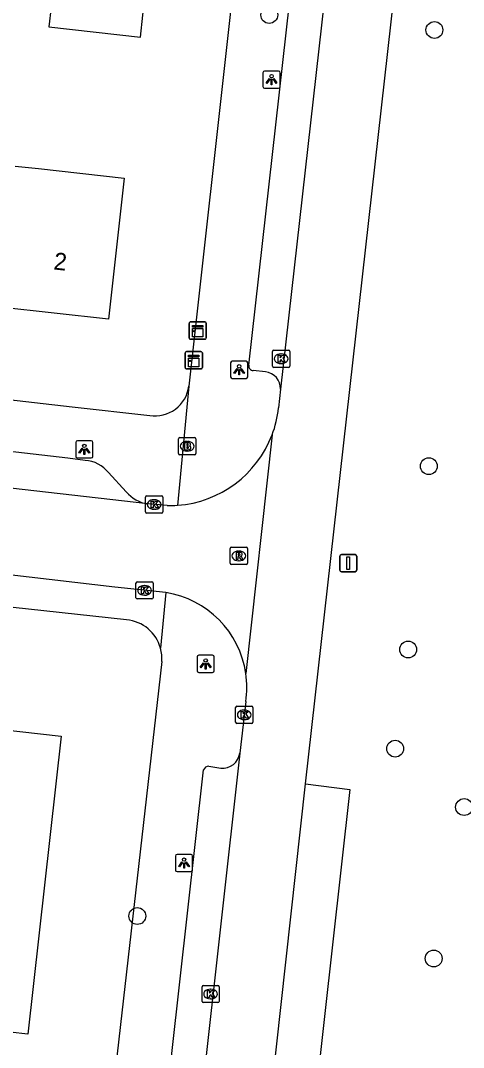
# Model space of a CAD drawing. Extents: x 161928 to 163055, y 386475 to 387428.
# Drawn here: x 162285.4 to 162311.1, y 387004.7 to 387064.4 of the extents above; entities that cross this region are included whole.
import ezdxf

# ---------------------------------------------------------------- set-up
doc = ezdxf.new("R2010")
doc.units = 0
for name, color, linetype in [('IMGEO_Boom', 7, 'Continuous'), ('IMGEO_Brandkraan', 7, 'Continuous'), ('IMGEO_Kast', 7, 'Continuous'), ('IMGEO_Kolk', 7, 'Continuous'), ('IMGEO_Lichtpunt', 7, 'Continuous'), ('IMGEO_Pand', 7, 'Continuous'), ('IMGEO_Pand_nummerreeks', 7, 'Continuous'), ('IMGEO_Parkeervlak_open', 7, 'Continuous'), ('IMGEO_Rijbaan_lokaal_open', 7, 'Continuous'), ('IMGEO_Rioolput', 7, 'Continuous'), ('IMGEO_Verkeersbordpaal', 7, 'Continuous'), ('IMGEO_Voetpad_open', 7, 'Continuous')]:
    doc.layers.add(name, color=color, linetype=linetype)

msp = doc.modelspace()

# ---------------------------------------------------------------- linework, layer by layer
at = {"layer": 'IMGEO_Boom'}
for centre in [(162299.864, 387064.689), (162309.455, 387063.817), (162309.128, 387038.487), (162307.931, 387027.834), (162307.177, 387022.077), (162311.177, 387018.684), (162292.201, 387012.356), (162309.414, 387009.889)]:
    msp.add_circle(centre, 0.489, dxfattribs=at)
at = {"layer": 'IMGEO_Brandkraan'}
for p, q in [((162294.599, 387039.214), (162294.599, 387040.066)), ((162294.674, 387040.14), (162295.526, 387040.14)), ((162295.6, 387040.066), (162295.6, 387039.214)), ((162295.087, 387039.92), (162295.112, 387039.92)), ((162295.526, 387039.14), (162294.674, 387039.14)), ((162295.11, 387039.36), (162295.085, 387039.36))]:
    msp.add_line(p, q, dxfattribs=at)
for points in [[(162294.599, 387039.214), (162294.599, 387040.066)], [(162294.674, 387040.14), (162295.526, 387040.14)], [(162295.6, 387040.066), (162295.6, 387039.214)], [(162294.947, 387039.84), (162294.947, 387039.44), (162295.16, 387039.44)], [(162295.178, 387039.84), (162294.947, 387039.84)], [(162295.126, 387039.759), (162295.072, 387039.759), (162295.072, 387039.683)], [(162295.072, 387039.683), (162295.125, 387039.683)], [(162295.134, 387039.607), (162295.072, 387039.607), (162295.072, 387039.526)], [(162295.072, 387039.526), (162295.134, 387039.526)], [(162295.526, 387039.14), (162294.674, 387039.14)]]:
    msp.add_lwpolyline(points, dxfattribs=at)
for centre, radius, start, end in [((162294.676, 387040.064), 0.0765, 91.55205, 178.44795), ((162294.676, 387040.064), 0.0765, 91.55205, 178.44795), ((162295.524, 387040.064), 0.0765, 1.55205, 88.44795), ((162295.524, 387040.064), 0.0765, 1.55205, 88.44795), ((162295.127, 387039.721), 0.0379, 267.82845, 90.93552), ((162295.135, 387039.566), 0.0404, 269.87594, 90.50774), ((162295.166, 387039.691), 0.251, 268.66757, 293.53466), ((162295.182, 387039.695), 0.145, 59.4692, 91.53667), ((162295.207, 387039.742), 0.0922, 285.51372, 58.15012), ((162295.212, 387039.55), 0.105, 301.31148, 78.98903), ((162294.676, 387039.216), 0.0765, 181.55205, 268.44795), ((162294.676, 387039.216), 0.0765, 181.55205, 268.44795), ((162295.524, 387039.216), 0.0765, 271.55205, 358.44795), ((162295.524, 387039.216), 0.0765, 271.55205, 358.44795)]:
    msp.add_arc(centre, radius, start, end, dxfattribs=at)
for centre, major_axis, ratio, start_param, end_param in [((162295.086, 387039.64), (-0.387, 0.002), 0.722429, 4.712389, 7.853982), ((162295.111, 387039.64), (-0.39, 0.002), 0.717154, 1.570796, 4.712389)]:
    msp.add_ellipse(centre, major_axis=major_axis, ratio=ratio, start_param=start_param, end_param=end_param, dxfattribs=at)
at = {"layer": 'IMGEO_Kast'}
for p, q in [((162295.206, 387045.935), (162295.206, 387046.776)), ((162295.206, 387046.776), (162295.206, 387045.935)), ((162295.281, 387046.86), (162296.122, 387046.86)), ((162296.122, 387046.86), (162295.281, 387046.86)), ((162296.206, 387046.785), (162296.206, 387045.944)), ((162296.206, 387045.944), (162296.206, 387046.785)), ((162296.131, 387045.86), (162295.29, 387045.86)), ((162295.29, 387045.86), (162296.131, 387045.86)), ((162294.982, 387044.209), (162294.982, 387045.05)), ((162294.982, 387045.05), (162294.982, 387044.209)), ((162295.057, 387045.134), (162295.898, 387045.134)), ((162295.898, 387045.134), (162295.057, 387045.134)), ((162295.982, 387045.059), (162295.982, 387044.218)), ((162295.982, 387044.218), (162295.982, 387045.059)), ((162295.907, 387044.134), (162295.066, 387044.134)), ((162295.066, 387044.134), (162295.907, 387044.134))]:
    msp.add_line(p, q, dxfattribs=at)
for points in [[(162295.401, 387046.65), (162296.001, 387046.65), (162296.001, 387046.565), (162295.401, 387046.565), (162295.401, 387046.65)], [(162295.401, 387046.475), (162296.001, 387046.475), (162296.001, 387045.986), (162295.401, 387045.986), (162295.401, 387046.475)], [(162295.177, 387044.924), (162295.777, 387044.924), (162295.777, 387044.839), (162295.177, 387044.839), (162295.177, 387044.924)], [(162295.177, 387044.749), (162295.777, 387044.749), (162295.777, 387044.26), (162295.177, 387044.26), (162295.177, 387044.749)]]:
    msp.add_lwpolyline(points, dxfattribs=at)
for centre in [(162295.485, 387046.324), (162295.261, 387044.598)]:
    msp.add_circle(centre, 0.0377, dxfattribs=at)
for centre, start, end in [((162295.284, 387046.782), 92.4484, 184.28452), ((162295.284, 387046.782), 92.4484, 184.28452), ((162296.128, 387046.782), 2.4484, 94.28452), ((162296.128, 387046.782), 2.4484, 94.28452), ((162295.284, 387045.938), 182.4484, 274.28452), ((162295.284, 387045.938), 182.4484, 274.28452), ((162296.128, 387045.938), 272.4484, 4.28452), ((162296.128, 387045.938), 272.4484, 4.28452), ((162295.06, 387045.056), 92.4484, 184.28452), ((162295.06, 387045.056), 92.4484, 184.28452), ((162295.904, 387045.056), 2.4484, 94.28452), ((162295.904, 387045.056), 2.4484, 94.28452), ((162295.06, 387044.212), 182.4484, 274.28452), ((162295.06, 387044.212), 182.4484, 274.28452), ((162295.904, 387044.212), 272.4484, 4.28452), ((162295.904, 387044.212), 272.4484, 4.28452)]:
    msp.add_arc(centre, 0.0779, start, end, dxfattribs=at)
at = {"layer": 'IMGEO_Kolk'}
for p, q in [((162300.052, 387044.298), (162300.052, 387045.15)), ((162300.127, 387045.224), (162300.979, 387045.224)), ((162300.54, 387045.004), (162300.565, 387045.004)), ((162301.053, 387045.15), (162301.053, 387044.298)), ((162300.979, 387044.224), (162300.127, 387044.224)), ((162300.563, 387044.444), (162300.538, 387044.444)), ((162292.683, 387035.832), (162292.683, 387036.684)), ((162292.758, 387036.758), (162293.61, 387036.758)), ((162293.171, 387036.538), (162293.196, 387036.538)), ((162293.684, 387036.684), (162293.684, 387035.832)), ((162293.194, 387035.978), (162293.169, 387035.978)), ((162293.61, 387035.758), (162292.758, 387035.758)), ((162292.124, 387030.845), (162292.124, 387031.697)), ((162292.199, 387031.771), (162293.051, 387031.771)), ((162293.125, 387031.697), (162293.125, 387030.845)), ((162292.612, 387031.551), (162292.637, 387031.551)), ((162293.051, 387030.771), (162292.199, 387030.771)), ((162292.635, 387030.991), (162292.61, 387030.991)), ((162297.988, 387024.541), (162298.84, 387024.541)), ((162297.913, 387023.615), (162297.913, 387024.467)), ((162298.401, 387024.321), (162298.426, 387024.321)), ((162298.914, 387024.467), (162298.914, 387023.615)), ((162298.84, 387023.541), (162297.988, 387023.541)), ((162298.424, 387023.761), (162298.399, 387023.761)), ((162295.959, 387007.4), (162295.959, 387008.252)), ((162296.034, 387008.326), (162296.886, 387008.326)), ((162296.447, 387008.106), (162296.472, 387008.106)), ((162296.96, 387008.252), (162296.96, 387007.4)), ((162296.886, 387007.326), (162296.034, 387007.326)), ((162296.47, 387007.546), (162296.445, 387007.546))]:
    msp.add_line(p, q, dxfattribs=at)
for points in [[(162300.052, 387044.298), (162300.052, 387045.15)], [(162300.127, 387045.224), (162300.979, 387045.224)], [(162300.373, 387044.924), (162300.496, 387044.924), (162300.496, 387044.773), (162300.626, 387044.924), (162300.79, 387044.924), (162300.644, 387044.773), (162300.797, 387044.524), (162300.645, 387044.524), (162300.56, 387044.688), (162300.496, 387044.621), (162300.496, 387044.524), (162300.373, 387044.524), (162300.373, 387044.924)], [(162301.053, 387045.15), (162301.053, 387044.298)], [(162300.979, 387044.224), (162300.127, 387044.224)], [(162292.683, 387035.832), (162292.683, 387036.684)], [(162292.758, 387036.758), (162293.61, 387036.758)], [(162293.004, 387036.458), (162293.127, 387036.458), (162293.127, 387036.307), (162293.257, 387036.458), (162293.421, 387036.458), (162293.275, 387036.307), (162293.428, 387036.058), (162293.276, 387036.058), (162293.191, 387036.222), (162293.127, 387036.155), (162293.127, 387036.058), (162293.004, 387036.058), (162293.004, 387036.458)], [(162293.684, 387036.684), (162293.684, 387035.832)], [(162293.61, 387035.758), (162292.758, 387035.758)], [(162292.124, 387030.845), (162292.124, 387031.697)], [(162292.199, 387031.771), (162293.051, 387031.771)], [(162293.125, 387031.697), (162293.125, 387030.845)], [(162292.445, 387031.471), (162292.568, 387031.471), (162292.568, 387031.32), (162292.698, 387031.471), (162292.862, 387031.471), (162292.716, 387031.32), (162292.869, 387031.071), (162292.717, 387031.071), (162292.632, 387031.235), (162292.568, 387031.168), (162292.568, 387031.071), (162292.445, 387031.071), (162292.445, 387031.471)], [(162293.051, 387030.771), (162292.199, 387030.771)], [(162297.988, 387024.541), (162298.84, 387024.541)], [(162297.913, 387023.615), (162297.913, 387024.467)], [(162298.234, 387024.241), (162298.357, 387024.241), (162298.357, 387024.09), (162298.487, 387024.241), (162298.651, 387024.241), (162298.505, 387024.09), (162298.658, 387023.841), (162298.506, 387023.841), (162298.421, 387024.005), (162298.357, 387023.938), (162298.357, 387023.841), (162298.234, 387023.841), (162298.234, 387024.241)], [(162298.914, 387024.467), (162298.914, 387023.615)], [(162298.84, 387023.541), (162297.988, 387023.541)], [(162295.959, 387007.4), (162295.959, 387008.252)], [(162296.034, 387008.326), (162296.886, 387008.326)], [(162296.28, 387008.026), (162296.403, 387008.026), (162296.403, 387007.875), (162296.533, 387008.026), (162296.697, 387008.026), (162296.551, 387007.875), (162296.704, 387007.626), (162296.552, 387007.626), (162296.467, 387007.79), (162296.403, 387007.723), (162296.403, 387007.626), (162296.28, 387007.626), (162296.28, 387008.026)], [(162296.96, 387008.252), (162296.96, 387007.4)], [(162296.886, 387007.326), (162296.034, 387007.326)]]:
    msp.add_lwpolyline(points, dxfattribs=at)
for centre, start, end in [((162300.129, 387045.148), 91.55205, 178.44795), ((162300.129, 387045.148), 91.55205, 178.44795), ((162300.977, 387045.148), 1.55205, 88.44795), ((162300.977, 387045.148), 1.55205, 88.44795), ((162300.129, 387044.3), 181.55205, 268.44795), ((162300.129, 387044.3), 181.55205, 268.44795), ((162300.977, 387044.3), 271.55205, 358.44795), ((162300.977, 387044.3), 271.55205, 358.44795), ((162292.76, 387036.682), 91.55205, 178.44795), ((162292.76, 387036.682), 91.55205, 178.44795), ((162293.608, 387036.682), 1.55205, 88.44795), ((162293.608, 387036.682), 1.55205, 88.44795), ((162292.76, 387035.834), 181.55205, 268.44795), ((162292.76, 387035.834), 181.55205, 268.44795), ((162293.608, 387035.834), 271.55205, 358.44795), ((162293.608, 387035.834), 271.55205, 358.44795), ((162292.201, 387031.695), 91.55205, 178.44795), ((162292.201, 387031.695), 91.55205, 178.44795), ((162293.049, 387031.695), 1.55205, 88.44795), ((162293.049, 387031.695), 1.55205, 88.44795), ((162292.201, 387030.847), 181.55205, 268.44795), ((162292.201, 387030.847), 181.55205, 268.44795), ((162293.049, 387030.847), 271.55205, 358.44795), ((162293.049, 387030.847), 271.55205, 358.44795), ((162297.99, 387024.465), 91.55205, 178.44795), ((162297.99, 387024.465), 91.55205, 178.44795), ((162298.838, 387024.465), 1.55205, 88.44795), ((162298.838, 387024.465), 1.55205, 88.44795), ((162297.99, 387023.617), 181.55205, 268.44795), ((162297.99, 387023.617), 181.55205, 268.44795), ((162298.838, 387023.617), 271.55205, 358.44795), ((162298.838, 387023.617), 271.55205, 358.44795), ((162296.036, 387008.25), 91.55205, 178.44795), ((162296.036, 387008.25), 91.55205, 178.44795), ((162296.884, 387008.25), 1.55205, 88.44795), ((162296.884, 387008.25), 1.55205, 88.44795), ((162296.036, 387007.402), 181.55205, 268.44795), ((162296.036, 387007.402), 181.55205, 268.44795), ((162296.884, 387007.402), 271.55205, 358.44795), ((162296.884, 387007.402), 271.55205, 358.44795)]:
    msp.add_arc(centre, 0.0765, start, end, dxfattribs=at)
for centre, major_axis, ratio, start_param, end_param in [((162300.539, 387044.724), (-0.387, 0.002), 0.722429, 4.712389, 7.853982), ((162300.564, 387044.724), (-0.39, 0.002), 0.717154, 1.570796, 4.712389), ((162293.17, 387036.258), (-0.387, 0.002), 0.722429, 4.712389, 7.853982), ((162293.195, 387036.258), (-0.39, 0.002), 0.717154, 1.570796, 4.712389), ((162292.611, 387031.271), (-0.387, 0.002), 0.722429, 4.712389, 7.853982), ((162292.636, 387031.271), (-0.39, 0.002), 0.717154, 1.570796, 4.712389), ((162298.4, 387024.041), (-0.387, 0.002), 0.722429, 4.712389, 7.853982), ((162298.425, 387024.041), (-0.39, 0.002), 0.717154, 1.570796, 4.712389), ((162296.446, 387007.826), (-0.387, 0.002), 0.722429, 4.712389, 7.853982), ((162296.471, 387007.826), (-0.39, 0.002), 0.717154, 1.570796, 4.712389)]:
    msp.add_ellipse(centre, major_axis=major_axis, ratio=ratio, start_param=start_param, end_param=end_param, dxfattribs=at)
at = {"layer": 'IMGEO_Lichtpunt'}
for p, q in [((162299.5, 387061.338), (162299.5, 387060.531)), ((162299.5, 387061.338), (162299.5, 387060.531)), ((162300.402, 387061.433), (162299.594, 387061.433)), ((162300.402, 387061.433), (162299.594, 387061.433)), ((162300.496, 387060.531), (162300.496, 387061.338)), ((162300.496, 387060.531), (162300.496, 387061.338)), ((162299.594, 387060.437), (162300.402, 387060.437)), ((162299.594, 387060.437), (162300.402, 387060.437)), ((162297.618, 387044.486), (162297.618, 387043.679)), ((162297.618, 387044.486), (162297.618, 387043.679)), ((162298.52, 387044.581), (162297.712, 387044.581)), ((162298.52, 387044.581), (162297.712, 387044.581)), ((162298.614, 387043.679), (162298.614, 387044.486)), ((162298.614, 387043.679), (162298.614, 387044.486)), ((162297.712, 387043.585), (162298.52, 387043.585)), ((162297.712, 387043.585), (162298.52, 387043.585)), ((162288.626, 387039.861), (162288.626, 387039.054)), ((162288.626, 387039.861), (162288.626, 387039.054)), ((162289.528, 387039.956), (162288.72, 387039.956)), ((162289.528, 387039.956), (162288.72, 387039.956)), ((162289.622, 387039.054), (162289.622, 387039.861)), ((162289.622, 387039.054), (162289.622, 387039.861)), ((162288.72, 387038.96), (162289.528, 387038.96)), ((162288.72, 387038.96), (162289.528, 387038.96)), ((162296.576, 387027.499), (162295.768, 387027.499)), ((162296.576, 387027.499), (162295.768, 387027.499)), ((162295.674, 387027.404), (162295.674, 387026.597)), ((162295.674, 387027.404), (162295.674, 387026.597)), ((162296.67, 387026.597), (162296.67, 387027.404)), ((162296.67, 387026.597), (162296.67, 387027.404)), ((162295.768, 387026.503), (162296.576, 387026.503)), ((162295.768, 387026.503), (162296.576, 387026.503)), ((162294.419, 387015.836), (162294.419, 387015.029)), ((162294.419, 387015.836), (162294.419, 387015.029)), ((162295.321, 387015.931), (162294.513, 387015.931)), ((162295.321, 387015.931), (162294.513, 387015.931)), ((162295.415, 387015.029), (162295.415, 387015.836)), ((162295.415, 387015.029), (162295.415, 387015.836)), ((162294.513, 387014.935), (162295.321, 387014.935)), ((162294.513, 387014.935), (162295.321, 387014.935))]:
    msp.add_line(p, q, dxfattribs=at)
for points in [[(162299.874, 387061.002), (162299.913, 387060.974), (162299.725, 387060.712), (162299.687, 387060.739), (162299.874, 387061.002)], [(162299.976, 387060.954), (162300.023, 387060.954), (162300.023, 387060.632), (162299.976, 387060.632), (162299.976, 387060.954)], [(162300.086, 387060.974), (162300.124, 387061.001), (162300.311, 387060.739), (162300.272, 387060.711), (162300.086, 387060.974)], [(162297.992, 387044.15), (162298.031, 387044.122), (162297.843, 387043.86), (162297.805, 387043.887), (162297.992, 387044.15)], [(162298.094, 387044.102), (162298.141, 387044.102), (162298.141, 387043.78), (162298.094, 387043.78), (162298.094, 387044.102)], [(162298.204, 387044.122), (162298.242, 387044.149), (162298.429, 387043.887), (162298.39, 387043.859), (162298.204, 387044.122)], [(162289, 387039.525), (162289.039, 387039.497), (162288.851, 387039.235), (162288.813, 387039.262), (162289, 387039.525)], [(162289.102, 387039.477), (162289.149, 387039.477), (162289.149, 387039.155), (162289.102, 387039.155), (162289.102, 387039.477)], [(162289.212, 387039.497), (162289.25, 387039.524), (162289.437, 387039.262), (162289.398, 387039.234), (162289.212, 387039.497)], [(162296.048, 387027.068), (162296.087, 387027.04), (162295.899, 387026.778), (162295.861, 387026.805), (162296.048, 387027.068)], [(162296.15, 387027.02), (162296.197, 387027.02), (162296.197, 387026.698), (162296.15, 387026.698), (162296.15, 387027.02)], [(162296.26, 387027.04), (162296.298, 387027.067), (162296.485, 387026.805), (162296.446, 387026.777), (162296.26, 387027.04)], [(162294.793, 387015.5), (162294.832, 387015.472), (162294.644, 387015.21), (162294.606, 387015.237), (162294.793, 387015.5)], [(162294.895, 387015.452), (162294.942, 387015.452), (162294.942, 387015.13), (162294.895, 387015.13), (162294.895, 387015.452)], [(162295.005, 387015.472), (162295.043, 387015.499), (162295.23, 387015.237), (162295.191, 387015.209), (162295.005, 387015.472)]]:
    msp.add_lwpolyline(points, dxfattribs=at)
for centre in [(162299.999, 387061.136), (162298.117, 387044.284), (162289.125, 387039.659), (162296.173, 387027.202), (162294.918, 387015.634)]:
    msp.add_circle(centre, 0.0994, dxfattribs=at)
for centre, start, end in [((162299.594, 387061.338), 90, 180), ((162299.594, 387061.338), 90, 180), ((162300.402, 387061.338), 0, 90), ((162300.402, 387061.338), 0, 90), ((162299.594, 387060.531), 180, 270), ((162299.594, 387060.531), 180, 270), ((162300.402, 387060.531), 270, 0), ((162300.402, 387060.531), 270, 360), ((162297.712, 387044.486), 90, 180), ((162297.712, 387044.486), 90, 180), ((162298.52, 387044.486), 0, 90), ((162298.52, 387044.486), 0, 90), ((162297.712, 387043.679), 180, 270), ((162297.712, 387043.679), 180, 270), ((162298.52, 387043.679), 270, 0), ((162298.52, 387043.679), 270, 360), ((162288.72, 387039.861), 90, 180), ((162288.72, 387039.861), 90, 180), ((162289.528, 387039.861), 0, 90), ((162289.528, 387039.861), 0, 90), ((162288.72, 387039.054), 180, 270), ((162288.72, 387039.054), 180, 270), ((162289.528, 387039.054), 270, 0), ((162289.528, 387039.054), 270, 360), ((162295.768, 387027.404), 90, 180), ((162295.768, 387027.404), 90, 180), ((162296.576, 387027.404), 0, 90), ((162296.576, 387027.404), 0, 90), ((162295.768, 387026.597), 180, 270), ((162295.768, 387026.597), 180, 270), ((162296.576, 387026.597), 270, 0), ((162296.576, 387026.597), 270, 360), ((162294.513, 387015.836), 90, 180), ((162294.513, 387015.836), 90, 180), ((162295.321, 387015.836), 0, 90), ((162295.321, 387015.836), 0, 90), ((162294.513, 387015.029), 180, 270), ((162294.513, 387015.029), 180, 270), ((162295.321, 387015.029), 270, 0), ((162295.321, 387015.029), 270, 360)]:
    msp.add_arc(centre, 0.0946, start, end, dxfattribs=at)
at = {"layer": 'IMGEO_Pand'}
for points in [[(162287.329, 387066.347), (162287.066, 387064.003), (162292.38, 387063.408), (162292.667, 387065.968)], [(162285.114, 387055.914), (162286.469, 387055.764), (162291.438, 387055.212), (162290.528, 387047.022), (162284.204, 387047.724)], [(162271.046, 387016.413), (162271.412, 387019.683), (162270.574, 387019.777), (162270.689, 387020.81), (162271.548, 387020.714), (162271.979, 387024.574), (162287.783, 387022.808), (162285.849, 387005.499), (162277.625, 387006.418), (162277.472, 387005.048), (162268.663, 387006.033)]]:
    msp.add_lwpolyline(points, dxfattribs=at)
at = {"layer": 'IMGEO_Parkeervlak_open'}
msp.add_lwpolyline([(162301.966, 387020.029), (162304.536, 387019.704), (162302.547, 387001.835), (162299.988, 387002.128)], dxfattribs=at)
at = {"layer": 'IMGEO_Rijbaan_lokaal_open'}
for points in [[(162309.861, 387125.998), (162300.517, 387042.959)], [(162301.966, 387020.029), (162309.685, 387088.77)], [(162292.807, 387036.295), (162209.297, 387045.816)], [(162300.517, 387042.959), (162300.407, 387041.864)], [(162300.028, 387040.299), (162298.503, 387026.445)], [(162293.928, 387036.193), (162292.807, 387036.295)], [(162293.855, 387031.139), (162290.902, 387031.456), (162256.711, 387035.451)], [(162298.5, 387024.808), (162298.15, 387021.823)], [(162298.15, 387021.823), (162295.968, 387002.165), (162294.227, 386986.475)], [(162299.988, 387002.128), (162301.966, 387020.029)]]:
    msp.add_lwpolyline(points, dxfattribs=at)
for centre, radius, start, end in [((162294.072, 387042.57), 6.374, 339.13025, 353.64301), ((162294.065, 387042.574), 6.382, 274.23289, 339.11867), ((162294.058, 387042.803), 6.611, 268.8711, 274.14377), ((162292.992, 387025.636), 5.57, 8.35079, 81.08496), ((162292.995, 387025.637), 5.567, 351.44016, 8.34984)]:
    msp.add_arc(centre, radius, start, end, dxfattribs=at)
at = {"layer": 'IMGEO_Rioolput'}
for p, q in [((162297.598, 387032.848), (162297.598, 387033.7)), ((162297.673, 387033.774), (162298.525, 387033.774)), ((162298.086, 387033.554), (162298.111, 387033.554)), ((162298.599, 387033.7), (162298.599, 387032.848)), ((162298.109, 387032.994), (162298.084, 387032.994)), ((162298.525, 387032.774), (162297.673, 387032.774))]:
    msp.add_line(p, q, dxfattribs=at)
for points in [[(162297.598, 387032.848), (162297.598, 387033.7)], [(162297.673, 387033.774), (162298.525, 387033.774)], [(162298.187, 387033.472), (162297.935, 387033.474), (162297.935, 387033.074)], [(162298.599, 387033.7), (162298.599, 387032.848)], [(162297.935, 387033.074), (162298.059, 387033.074), (162298.059, 387033.236), (162298.07, 387033.236)], [(162298.113, 387033.393), (162298.059, 387033.393), (162298.059, 387033.312)], [(162298.059, 387033.312), (162298.111, 387033.312)], [(162298.117, 387033.207), (162298.188, 387033.074), (162298.328, 387033.074), (162298.263, 387033.2)], [(162298.525, 387032.774), (162297.673, 387032.774)]]:
    msp.add_lwpolyline(points, dxfattribs=at)
for centre, radius, start, end in [((162297.675, 387033.698), 0.0765, 91.55205, 178.44795), ((162297.675, 387033.698), 0.0765, 91.55205, 178.44795), ((162298.186, 387033.362), 0.109, 350.36119, 89.41601), ((162298.523, 387033.698), 0.0765, 1.55205, 88.44795), ((162298.523, 387033.698), 0.0765, 1.55205, 88.44795), ((162297.675, 387032.85), 0.0765, 181.55205, 268.44795), ((162297.675, 387032.85), 0.0765, 181.55205, 268.44795), ((162298.069, 387033.183), 0.0533, 26.02933, 88.69889), ((162298.095, 387033.501), 0.19, 274.7715, 282.96867), ((162298.119, 387033.297), 0.0964, 77.00612, 93.18647), ((162298.133, 387033.354), 0.0378, 276.66336, 79.67722), ((162298.184, 387033.362), 0.112, 277.58423, 350.98172), ((162298.168, 387033.147), 0.108, 29.51342, 73.79051), ((162298.523, 387032.85), 0.0765, 271.55205, 358.44795), ((162298.523, 387032.85), 0.0765, 271.55205, 358.44795)]:
    msp.add_arc(centre, radius, start, end, dxfattribs=at)
for centre, major_axis, ratio, start_param, end_param in [((162298.085, 387033.274), (-0.387, 0.002), 0.722429, 4.712389, 7.853982), ((162298.11, 387033.274), (-0.39, 0.002), 0.717154, 1.570796, 4.712389)]:
    msp.add_ellipse(centre, major_axis=major_axis, ratio=ratio, start_param=start_param, end_param=end_param, dxfattribs=at)
at = {"layer": 'IMGEO_Verkeersbordpaal'}
for p, q in [((162303.958, 387032.452), (162303.958, 387033.252)), ((162303.958, 387033.252), (162303.958, 387032.452)), ((162304.058, 387033.352), (162304.848, 387033.352)), ((162304.848, 387033.352), (162304.058, 387033.352)), ((162304.948, 387033.252), (162304.948, 387032.452)), ((162304.948, 387032.452), (162304.948, 387033.252)), ((162304.848, 387032.352), (162304.058, 387032.352)), ((162304.058, 387032.352), (162304.848, 387032.352))]:
    msp.add_line(p, q, dxfattribs=at)
msp.add_lwpolyline([(162304.378, 387033.227), (162304.528, 387033.227), (162304.528, 387032.477), (162304.378, 387032.477), (162304.378, 387033.227)], dxfattribs=at)
for centre, start, end in [((162304.058, 387033.252), 90, 180), ((162304.058, 387033.252), 90, 180), ((162304.848, 387033.252), 0, 90), ((162304.848, 387033.252), 360, 90), ((162304.058, 387032.452), 180, 270), ((162304.058, 387032.452), 180, 270), ((162304.848, 387032.452), 270, 0), ((162304.848, 387032.452), 270, 0)]:
    msp.add_arc(centre, 0.1, start, end, dxfattribs=at)
at = {"layer": 'IMGEO_Voetpad_open'}
for points in [[(162298.684, 387044.352), (162307.745, 387125.029)], [(162297.677, 387065.408), (162295.188, 387043.126)], [(162202.596, 387051.794), (162288.423, 387041.928), (162292.928, 387041.432)], [(162289.168, 387038.822), (162288.165, 387038.944), (162213.325, 387047.577)], [(162299.645, 387043.96), (162298.937, 387044.037)], [(162295.188, 387043.126), (162294.536, 387036.209)], [(162291.563, 387036.991), (162290.537, 387038.11)], [(162291.581, 387029.555), (162256.179, 387033.419)], [(162293.855, 387031.139), (162293.551, 387027.906)], [(162293.618, 387027.136), (162290.321, 386998.054)], [(162296.352, 387021.064), (162297.053, 387020.942)], [(162292.361, 386987.901), (162296.049, 387020.839)]]:
    msp.add_lwpolyline(points, dxfattribs=at)
for centre, radius, start, end in [((162298.937, 387044.296), 0.259, 167.58802, 269.95307), ((162299.54, 387042.988), 0.978, 358.31233, 83.8078), ((162293.248, 387043.359), 1.954, 260.56818, 353.13916), ((162289.018, 387036.861), 1.967, 39.42372, 85.61951), ((162293.112, 387038.3), 2.028, 220.197, 261.35024), ((162291.394, 387027.33), 2.232, 14.94104, 85.19653), ((162291.389, 387027.33), 2.237, 355.02488, 14.92103), ((162297.15, 387021.945), 1.008, 264.4818, 353.05405), ((162296.376, 387020.715), 0.35, 93.99921, 159.19404)]:
    msp.add_arc(centre, radius, start, end, dxfattribs=at)

# ---------------------------------------------------------------- texts
at = {"layer": 'IMGEO_Pand_nummerreeks'}
msp.add_text('2', height=1, rotation=353.66447, dxfattribs=at).set_placement((162287.312, 387049.915))

doc.saveas('drawing.dxf')
